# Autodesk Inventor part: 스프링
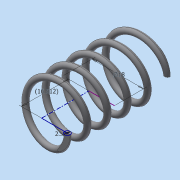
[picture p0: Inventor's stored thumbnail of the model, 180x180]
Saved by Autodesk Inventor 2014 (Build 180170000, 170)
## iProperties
Created: 2024-02
Part Number: 스프링
Material: 스테인레스 스틸
Document SubType Name: Modeling
Designer: dg
Density: 8.08 g/cm^3
Appearance: 반연마
Mass: 7.07035 g
Surface Area: 17.7554 cm^2
Volume: 0.875043 cm^3
Author: dg
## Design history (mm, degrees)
sketch "스케치1"
  geometry: L1 (0, 0)-(9, 0); L2 (0, 0)-(0, 28.5); L3 (0, 28.5)-(9, 28.5); C1 r 1 at (9, 0)
  constraints: 6 end point, 2 perpendicular, 1 centre point, 1 coincident, 1 horizontal, 1 parallel
  dimensions: "d0" = 28.5 distance of L1.start L2.end (derived); "d1" = 18 diameter of L3.end L2; "d2" = 2 diameter of C1
feature "코일1" pitch "d4" = 10; turns "d6" = 5; dims "d5" = 28.5 (= d0), "d7" = 0, angle "d8" = 90 deg, angle "d9" = 90 deg, "d10" = 0, "d11" = 0
node "작업 평면1"
feature "분할1"
feature "분할2"
node "솔리드1"
